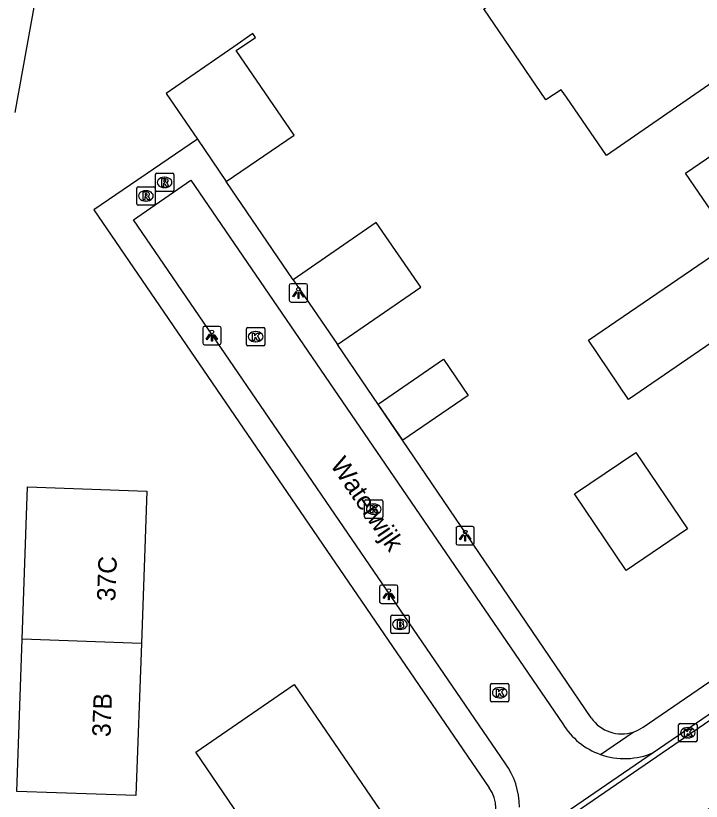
# Model space of a CAD drawing. Extents: x 155275 to 156263, y 382654 to 383635.
# Drawn here: x 155415.06 to 155452.36, y 383301.06 to 383343.77 of the extents above; entities that cross this region are included whole.
import ezdxf

# ---------------------------------------------------------------- set-up
doc = ezdxf.new("R2010")
doc.units = 0
for name, color, linetype in [('IMGEO_Brandkraan', 7, 'Continuous'), ('IMGEO_Kolk', 7, 'Continuous'), ('IMGEO_Lichtpunt', 7, 'Continuous'), ('IMGEO_Openbare_ruimte_label', 7, 'Continuous'), ('IMGEO_Pand', 7, 'Continuous'), ('IMGEO_Pand_nummerreeks', 7, 'Continuous'), ('IMGEO_Rijbaan_lokaal_open', 7, 'Continuous'), ('IMGEO_Rioolput', 7, 'Continuous'), ('IMGEO_Voetpad_open', 7, 'Continuous')]:
    doc.layers.add(name, color=color, linetype=linetype)

msp = doc.modelspace()

# ---------------------------------------------------------------- linework, layer by layer
at = {"layer": 'IMGEO_Brandkraan'}
for p, q in [((155435.463, 383310.256), (155435.463, 383311.108)), ((155435.538, 383311.182), (155436.39, 383311.182)), ((155436.464, 383311.108), (155436.464, 383310.256)), ((155435.951, 383310.962), (155435.976, 383310.962)), ((155435.974, 383310.402), (155435.949, 383310.402)), ((155436.39, 383310.182), (155435.538, 383310.182))]:
    msp.add_line(p, q, dxfattribs=at)
for points in [[(155435.463, 383310.256), (155435.463, 383311.108)], [(155435.538, 383311.182), (155436.39, 383311.182)], [(155436.464, 383311.108), (155436.464, 383310.256)], [(155435.811, 383310.882), (155435.811, 383310.482), (155436.024, 383310.482)], [(155436.042, 383310.882), (155435.811, 383310.882)], [(155435.99, 383310.801), (155435.936, 383310.801), (155435.936, 383310.725)], [(155435.936, 383310.725), (155435.989, 383310.725)], [(155435.998, 383310.649), (155435.936, 383310.649), (155435.936, 383310.568)], [(155435.936, 383310.568), (155435.998, 383310.568)], [(155436.39, 383310.182), (155435.538, 383310.182)]]:
    msp.add_lwpolyline(points, dxfattribs=at)
for centre, radius, start, end in [((155435.54, 383311.106), 0.0765, 91.552, 178.448), ((155435.54, 383311.106), 0.0765, 91.552, 178.448), ((155436.388, 383311.106), 0.0765, 1.552, 88.448), ((155436.388, 383311.106), 0.0765, 1.552, 88.448), ((155435.991, 383310.763), 0.0379, 267.8285, 90.9355), ((155436.046, 383310.737), 0.145, 59.4692, 91.5367), ((155436.071, 383310.784), 0.0922, 285.5137, 58.1501), ((155436.076, 383310.592), 0.105, 301.3115, 78.989), ((155435.54, 383310.258), 0.0765, 181.552, 268.448), ((155435.54, 383310.258), 0.0765, 181.552, 268.448), ((155435.999, 383310.608), 0.0404, 269.8759, 90.5077), ((155436.03, 383310.733), 0.251, 268.6676, 293.5347), ((155436.388, 383310.258), 0.0765, 271.552, 358.448), ((155436.388, 383310.258), 0.0765, 271.552, 358.448)]:
    msp.add_arc(centre, radius, start, end, dxfattribs=at)
for centre, major_axis, ratio, start_param, end_param in [((155435.95, 383310.682), (-0.387, 0.002), 0.722429, 4.712389, 7.853982), ((155435.975, 383310.682), (-0.39, 0.002), 0.717154, 1.570796, 4.712389)]:
    msp.add_ellipse(centre, major_axis=major_axis, ratio=ratio, start_param=start_param, end_param=end_param, dxfattribs=at)
at = {"layer": 'IMGEO_Kolk'}
for p, q in [((155427.619, 383325.892), (155427.619, 383326.744)), ((155427.694, 383326.818), (155428.546, 383326.818)), ((155428.107, 383326.598), (155428.132, 383326.598)), ((155428.62, 383326.744), (155428.62, 383325.892)), ((155428.13, 383326.038), (155428.105, 383326.038)), ((155428.546, 383325.818), (155427.694, 383325.818)), ((155434.04, 383316.517), (155434.04, 383317.369)), ((155434.115, 383317.443), (155434.967, 383317.443)), ((155434.528, 383317.223), (155434.553, 383317.223)), ((155435.041, 383317.369), (155435.041, 383316.517)), ((155434.551, 383316.663), (155434.526, 383316.663)), ((155434.967, 383316.443), (155434.115, 383316.443)), ((155440.892, 383306.541), (155440.892, 383307.393)), ((155440.967, 383307.467), (155441.819, 383307.467)), ((155441.38, 383307.247), (155441.405, 383307.247)), ((155441.893, 383307.393), (155441.893, 383306.541)), ((155441.819, 383306.467), (155440.967, 383306.467)), ((155441.403, 383306.687), (155441.378, 383306.687)), ((155451.127, 383304.363), (155451.127, 383305.215)), ((155451.202, 383305.289), (155452.054, 383305.289)), ((155452.128, 383305.215), (155452.128, 383304.363)), ((155451.615, 383305.069), (155451.64, 383305.069)), ((155452.054, 383304.289), (155451.202, 383304.289)), ((155451.638, 383304.509), (155451.613, 383304.509))]:
    msp.add_line(p, q, dxfattribs=at)
for points in [[(155427.619, 383325.892), (155427.619, 383326.744)], [(155427.694, 383326.818), (155428.546, 383326.818)], [(155427.94, 383326.518), (155428.063, 383326.518), (155428.063, 383326.367), (155428.193, 383326.518), (155428.357, 383326.518), (155428.211, 383326.367), (155428.364, 383326.118), (155428.212, 383326.118), (155428.127, 383326.282), (155428.063, 383326.215), (155428.063, 383326.118), (155427.94, 383326.118), (155427.94, 383326.518)], [(155428.62, 383326.744), (155428.62, 383325.892)], [(155428.546, 383325.818), (155427.694, 383325.818)], [(155434.04, 383316.517), (155434.04, 383317.369)], [(155434.115, 383317.443), (155434.967, 383317.443)], [(155434.361, 383317.143), (155434.484, 383317.143), (155434.484, 383316.992), (155434.614, 383317.143), (155434.778, 383317.143), (155434.632, 383316.992), (155434.785, 383316.743), (155434.633, 383316.743), (155434.548, 383316.907), (155434.484, 383316.84), (155434.484, 383316.743), (155434.361, 383316.743), (155434.361, 383317.143)], [(155435.041, 383317.369), (155435.041, 383316.517)], [(155434.967, 383316.443), (155434.115, 383316.443)], [(155440.892, 383306.541), (155440.892, 383307.393)], [(155440.967, 383307.467), (155441.819, 383307.467)], [(155441.893, 383307.393), (155441.893, 383306.541)], [(155441.213, 383307.167), (155441.336, 383307.167), (155441.336, 383307.016), (155441.466, 383307.167), (155441.63, 383307.167), (155441.484, 383307.016), (155441.637, 383306.767), (155441.485, 383306.767), (155441.4, 383306.931), (155441.336, 383306.864), (155441.336, 383306.767), (155441.213, 383306.767), (155441.213, 383307.167)], [(155441.819, 383306.467), (155440.967, 383306.467)], [(155451.127, 383304.363), (155451.127, 383305.215)], [(155451.202, 383305.289), (155452.054, 383305.289)], [(155452.128, 383305.215), (155452.128, 383304.363)], [(155451.448, 383304.989), (155451.571, 383304.989), (155451.571, 383304.838), (155451.701, 383304.989), (155451.865, 383304.989), (155451.719, 383304.838), (155451.872, 383304.589), (155451.72, 383304.589), (155451.635, 383304.753), (155451.571, 383304.686), (155451.571, 383304.589), (155451.448, 383304.589), (155451.448, 383304.989)], [(155452.054, 383304.289), (155451.202, 383304.289)]]:
    msp.add_lwpolyline(points, dxfattribs=at)
for centre, start, end in [((155427.696, 383326.742), 91.552, 178.448), ((155427.696, 383326.742), 91.552, 178.448), ((155428.544, 383326.742), 1.552, 88.448), ((155428.544, 383326.742), 1.552, 88.448), ((155427.696, 383325.894), 181.552, 268.448), ((155427.696, 383325.894), 181.552, 268.448), ((155428.544, 383325.894), 271.552, 358.448), ((155428.544, 383325.894), 271.552, 358.448), ((155434.117, 383317.367), 91.552, 178.448), ((155434.117, 383317.367), 91.552, 178.448), ((155434.965, 383317.367), 1.552, 88.448), ((155434.965, 383317.367), 1.552, 88.448), ((155434.117, 383316.519), 181.552, 268.448), ((155434.117, 383316.519), 181.552, 268.448), ((155434.965, 383316.519), 271.552, 358.448), ((155434.965, 383316.519), 271.552, 358.448), ((155440.969, 383307.391), 91.552, 178.448), ((155440.969, 383307.391), 91.552, 178.448), ((155441.817, 383307.391), 1.552, 88.448), ((155441.817, 383307.391), 1.552, 88.448), ((155440.969, 383306.543), 181.552, 268.448), ((155440.969, 383306.543), 181.552, 268.448), ((155441.817, 383306.543), 271.552, 358.448), ((155441.817, 383306.543), 271.552, 358.448), ((155451.204, 383305.213), 91.552, 178.448), ((155451.204, 383305.213), 91.552, 178.448), ((155452.052, 383305.213), 1.552, 88.448), ((155452.052, 383305.213), 1.552, 88.448), ((155451.204, 383304.365), 181.552, 268.448), ((155451.204, 383304.365), 181.552, 268.448), ((155452.052, 383304.365), 271.552, 358.448), ((155452.052, 383304.365), 271.552, 358.448)]:
    msp.add_arc(centre, 0.0765, start, end, dxfattribs=at)
for centre, major_axis, ratio, start_param, end_param in [((155428.106, 383326.318), (-0.387, 0.002), 0.722429, 4.712389, 7.853982), ((155428.131, 383326.318), (-0.39, 0.002), 0.717154, 1.570796, 4.712389), ((155434.527, 383316.943), (-0.387, 0.002), 0.722429, 4.712389, 7.853982), ((155434.552, 383316.943), (-0.39, 0.002), 0.717154, 1.570796, 4.712389), ((155441.379, 383306.967), (-0.387, 0.002), 0.722429, 4.712389, 7.853982), ((155441.404, 383306.967), (-0.39, 0.002), 0.717154, 1.570796, 4.712389), ((155451.614, 383304.789), (-0.387, 0.002), 0.722429, 4.712389, 7.853982), ((155451.639, 383304.789), (-0.39, 0.002), 0.717154, 1.570796, 4.712389)]:
    msp.add_ellipse(centre, major_axis=major_axis, ratio=ratio, start_param=start_param, end_param=end_param, dxfattribs=at)
at = {"layer": 'IMGEO_Lichtpunt'}
for p, q in [((155429.947, 383329.102), (155429.947, 383328.295)), ((155429.947, 383329.102), (155429.947, 383328.295)), ((155430.849, 383329.197), (155430.041, 383329.197)), ((155430.849, 383329.197), (155430.041, 383329.197)), ((155430.943, 383328.295), (155430.943, 383329.102)), ((155430.943, 383328.295), (155430.943, 383329.102)), ((155430.041, 383328.201), (155430.849, 383328.201)), ((155430.041, 383328.201), (155430.849, 383328.201)), ((155426.141, 383326.877), (155425.333, 383326.877)), ((155426.141, 383326.877), (155425.333, 383326.877)), ((155425.239, 383326.782), (155425.239, 383325.975)), ((155425.239, 383326.782), (155425.239, 383325.975)), ((155426.235, 383325.975), (155426.235, 383326.782)), ((155426.235, 383325.975), (155426.235, 383326.782)), ((155425.333, 383325.881), (155426.141, 383325.881)), ((155425.333, 383325.881), (155426.141, 383325.881)), ((155439.016, 383315.904), (155439.016, 383315.097)), ((155439.016, 383315.904), (155439.016, 383315.097)), ((155439.918, 383315.999), (155439.11, 383315.999)), ((155439.918, 383315.999), (155439.11, 383315.999)), ((155440.012, 383315.097), (155440.012, 383315.904)), ((155440.012, 383315.097), (155440.012, 383315.904)), ((155439.11, 383315.003), (155439.918, 383315.003)), ((155439.11, 383315.003), (155439.918, 383315.003)), ((155435.762, 383312.813), (155434.954, 383312.813)), ((155435.762, 383312.813), (155434.954, 383312.813)), ((155434.86, 383312.718), (155434.86, 383311.911)), ((155434.86, 383312.718), (155434.86, 383311.911)), ((155435.856, 383311.911), (155435.856, 383312.718)), ((155435.856, 383311.911), (155435.856, 383312.718)), ((155434.954, 383311.817), (155435.762, 383311.817)), ((155434.954, 383311.817), (155435.762, 383311.817))]:
    msp.add_line(p, q, dxfattribs=at)
for points in [[(155430.321, 383328.766), (155430.36, 383328.738), (155430.172, 383328.476), (155430.134, 383328.503), (155430.321, 383328.766)], [(155430.423, 383328.718), (155430.47, 383328.718), (155430.47, 383328.396), (155430.423, 383328.396), (155430.423, 383328.718)], [(155430.533, 383328.738), (155430.571, 383328.765), (155430.758, 383328.503), (155430.719, 383328.475), (155430.533, 383328.738)], [(155425.613, 383326.446), (155425.652, 383326.418), (155425.464, 383326.156), (155425.426, 383326.183), (155425.613, 383326.446)], [(155425.715, 383326.398), (155425.762, 383326.398), (155425.762, 383326.076), (155425.715, 383326.076), (155425.715, 383326.398)], [(155425.825, 383326.418), (155425.863, 383326.445), (155426.05, 383326.183), (155426.011, 383326.155), (155425.825, 383326.418)], [(155439.39, 383315.568), (155439.429, 383315.54), (155439.241, 383315.278), (155439.203, 383315.305), (155439.39, 383315.568)], [(155439.492, 383315.52), (155439.539, 383315.52), (155439.539, 383315.198), (155439.492, 383315.198), (155439.492, 383315.52)], [(155439.602, 383315.54), (155439.64, 383315.567), (155439.827, 383315.305), (155439.788, 383315.277), (155439.602, 383315.54)], [(155435.234, 383312.382), (155435.273, 383312.354), (155435.085, 383312.092), (155435.047, 383312.119), (155435.234, 383312.382)], [(155435.446, 383312.354), (155435.484, 383312.381), (155435.671, 383312.119), (155435.632, 383312.091), (155435.446, 383312.354)], [(155435.336, 383312.334), (155435.383, 383312.334), (155435.383, 383312.012), (155435.336, 383312.012), (155435.336, 383312.334)]]:
    msp.add_lwpolyline(points, dxfattribs=at)
for centre in [(155430.446, 383328.9), (155425.738, 383326.58), (155439.515, 383315.702), (155435.359, 383312.516)]:
    msp.add_circle(centre, 0.0994, dxfattribs=at)
for centre, start, end in [((155430.041, 383329.102), 90, 180), ((155430.041, 383329.102), 90, 180), ((155430.849, 383329.102), 0, 90), ((155430.849, 383329.102), 0, 90), ((155430.041, 383328.295), 180, 270), ((155430.041, 383328.295), 180, 270), ((155430.849, 383328.295), 270, 0), ((155430.849, 383328.295), 270, 360), ((155425.333, 383326.782), 90, 180), ((155425.333, 383326.782), 90, 180), ((155426.141, 383326.782), 0, 90), ((155426.141, 383326.782), 0, 90), ((155425.333, 383325.975), 180, 270), ((155425.333, 383325.975), 180, 270), ((155426.141, 383325.975), 270, 0), ((155426.141, 383325.975), 270, 360), ((155439.11, 383315.904), 90, 180), ((155439.11, 383315.904), 90, 180), ((155439.918, 383315.904), 0, 90), ((155439.918, 383315.904), 0, 90), ((155439.11, 383315.097), 180, 270), ((155439.11, 383315.097), 180, 270), ((155439.918, 383315.097), 270, 0), ((155439.918, 383315.097), 270, 360), ((155434.954, 383312.718), 90, 180), ((155434.954, 383312.718), 90, 180), ((155435.762, 383312.718), 0, 90), ((155435.762, 383312.718), 0, 90), ((155434.954, 383311.911), 180, 270), ((155434.954, 383311.911), 180, 270), ((155435.762, 383311.911), 270, 0), ((155435.762, 383311.911), 270, 360)]:
    msp.add_arc(centre, 0.0946, start, end, dxfattribs=at)
at = {"layer": 'IMGEO_Pand'}
for points in [[(155440.523, 383344.13), (155441.34, 383344.675), (155441.067, 383345.1), (155445.065, 383347.851), (155444.806, 383348.276), (155447.463, 383350.102), (155447.754, 383349.697), (155451.766, 383352.44), (155452.035, 383352.043), (155451.835, 383351.909), (155455.223, 383346.955), (155455.421, 383347.09), (155455.698, 383346.686), (155454.929, 383346.157), (155457.104, 383343.005), (155447.203, 383336.173), (155445.018, 383339.34), (155444.742, 383339.74), (155443.903, 383339.191), (155440.523, 383344.13)], [(155426.522, 383334.751), (155430.206, 383337.265), (155427.061, 383341.874), (155428.1, 383342.584), (155427.959, 383342.791), (155426.924, 383342.074), (155423.258, 383339.534), (155424.949, 383337.057)], [(155454.052, 383331.481), (155451.501, 383335.199), (155461.558, 383342.081), (155465.511, 383336.304), (155461.797, 383333.762), (155462.586, 383332.609), (155448.403, 383322.903), (155446.219, 383326.126), (155454.052, 383331.481)], [(155424.949, 383337.057), (155426.522, 383334.751)], [(155432.572, 383325.887), (155437.099, 383329.002), (155434.678, 383332.519), (155430.165, 383329.414)], [(155430.165, 383329.414), (155432.572, 383325.887)], [(155438.327, 383325.092), (155439.677, 383323.126), (155436.124, 383320.686), (155434.774, 383322.652), (155438.327, 383325.092)], [(155448.797, 383320.027), (155451.612, 383315.865), (155448.28, 383313.611), (155445.465, 383317.773), (155448.797, 383320.027)], [(155415.414, 383309.879), (155415.709, 383318.158), (155422.199, 383317.925), (155421.902, 383309.648)], [(155421.902, 383309.648), (155421.606, 383301.375), (155415.119, 383301.6), (155415.414, 383309.879)], [(155421.902, 383309.648), (155415.414, 383309.879)], [(155430.22, 383307.405), (155435.86, 383299.176), (155433.637, 383297.63), (155430.508, 383295.453), (155424.855, 383303.729), (155430.22, 383307.405)]]:
    msp.add_lwpolyline(points, dxfattribs=at)
at = {"layer": 'IMGEO_Rijbaan_lokaal_open'}
for points in [[(155545.973, 383369.225), (155512.791, 383346.508), (155450.858, 383304.106), (155413.779, 383278.713), (155415.989, 383275.504), (155453.502, 383301.158), (155500.38, 383333.268), (155548.143, 383365.998)], [(155449.748, 383303.711), (155450.724, 383304.38), (155450.774, 383304.414), (155508.223, 383343.736)], [(155441.686, 383303.132), (155421.478, 383332.678), (155424.588, 383334.829), (155444.824, 383305.278)], [(155441.154, 383297.824), (155449.748, 383303.711)]]:
    msp.add_lwpolyline(points, dxfattribs=at)
for centre, radius, start, end in [((155448.188, 383307.32), 3.935, 211.2654, 250.4521), ((155448.184, 383307.302), 3.917, 250.4109, 293.5307), ((155438.476, 383300.77), 3.985, 359.7493, 36.3385)]:
    msp.add_arc(centre, radius, start, end, dxfattribs=at)
at = {"layer": 'IMGEO_Rioolput'}
for p, q in [((155422.663, 383334.276), (155422.663, 383335.128)), ((155422.738, 383335.202), (155423.59, 383335.202)), ((155423.664, 383335.128), (155423.664, 383334.276)), ((155423.151, 383334.982), (155423.176, 383334.982)), ((155421.645, 383333.543), (155421.645, 383334.395)), ((155421.72, 383334.469), (155422.572, 383334.469)), ((155422.133, 383334.249), (155422.158, 383334.249)), ((155422.646, 383334.395), (155422.646, 383333.543)), ((155423.59, 383334.202), (155422.738, 383334.202)), ((155423.174, 383334.422), (155423.149, 383334.422)), ((155422.572, 383333.469), (155421.72, 383333.469)), ((155422.156, 383333.689), (155422.131, 383333.689))]:
    msp.add_line(p, q, dxfattribs=at)
for points in [[(155422.663, 383334.276), (155422.663, 383335.128)], [(155422.738, 383335.202), (155423.59, 383335.202)], [(155423.664, 383335.128), (155423.664, 383334.276)], [(155423.252, 383334.9), (155423, 383334.902), (155423, 383334.502)], [(155423, 383334.502), (155423.124, 383334.502), (155423.124, 383334.664), (155423.135, 383334.664)], [(155423.178, 383334.821), (155423.124, 383334.821), (155423.124, 383334.74)], [(155423.124, 383334.74), (155423.176, 383334.74)], [(155423.182, 383334.635), (155423.253, 383334.502), (155423.393, 383334.502), (155423.328, 383334.628)], [(155421.645, 383333.543), (155421.645, 383334.395)], [(155421.72, 383334.469), (155422.572, 383334.469)], [(155422.234, 383334.167), (155421.982, 383334.169), (155421.982, 383333.769)], [(155422.646, 383334.395), (155422.646, 383333.543)], [(155423.59, 383334.202), (155422.738, 383334.202)], [(155421.982, 383333.769), (155422.106, 383333.769), (155422.106, 383333.931), (155422.117, 383333.931)], [(155422.16, 383334.088), (155422.106, 383334.088), (155422.106, 383334.007)], [(155422.106, 383334.007), (155422.158, 383334.007)], [(155422.164, 383333.902), (155422.235, 383333.769), (155422.375, 383333.769), (155422.31, 383333.895)], [(155422.572, 383333.469), (155421.72, 383333.469)]]:
    msp.add_lwpolyline(points, dxfattribs=at)
for centre, radius, start, end in [((155422.74, 383335.126), 0.0765, 91.552, 178.448), ((155422.74, 383335.126), 0.0765, 91.552, 178.448), ((155423.588, 383335.126), 0.0765, 1.552, 88.448), ((155423.588, 383335.126), 0.0765, 1.552, 88.448), ((155423.134, 383334.611), 0.0533, 26.0293, 88.6989), ((155423.16, 383334.929), 0.19, 274.7715, 282.9687), ((155423.184, 383334.725), 0.0964, 77.0061, 93.1865), ((155423.198, 383334.782), 0.0378, 276.6634, 79.6772), ((155423.251, 383334.79), 0.109, 350.3612, 89.416), ((155423.249, 383334.79), 0.112, 277.5842, 350.9817), ((155423.233, 383334.575), 0.108, 29.5134, 73.7905), ((155421.722, 383334.393), 0.0765, 91.552, 178.448), ((155421.722, 383334.393), 0.0765, 91.552, 178.448), ((155422.233, 383334.057), 0.109, 350.3612, 89.416), ((155422.57, 383334.393), 0.0765, 1.552, 88.448), ((155422.57, 383334.393), 0.0765, 1.552, 88.448), ((155422.74, 383334.278), 0.0765, 181.552, 268.448), ((155422.74, 383334.278), 0.0765, 181.552, 268.448), ((155423.588, 383334.278), 0.0765, 271.552, 358.448), ((155423.588, 383334.278), 0.0765, 271.552, 358.448), ((155422.116, 383333.878), 0.0533, 26.0293, 88.6989), ((155422.142, 383334.196), 0.19, 274.7715, 282.9687), ((155422.166, 383333.992), 0.0964, 77.0061, 93.1865), ((155422.18, 383334.049), 0.0378, 276.6634, 79.6772), ((155422.231, 383334.057), 0.112, 277.5842, 350.9817), ((155422.215, 383333.842), 0.108, 29.5134, 73.7905), ((155421.722, 383333.545), 0.0765, 181.552, 268.448), ((155421.722, 383333.545), 0.0765, 181.552, 268.448), ((155422.57, 383333.545), 0.0765, 271.552, 358.448), ((155422.57, 383333.545), 0.0765, 271.552, 358.448)]:
    msp.add_arc(centre, radius, start, end, dxfattribs=at)
for centre, major_axis, ratio, start_param, end_param in [((155423.15, 383334.702), (-0.387, 0.002), 0.722429, 4.712389, 7.853982), ((155423.175, 383334.702), (-0.39, 0.002), 0.717154, 1.570796, 4.712389), ((155422.132, 383333.969), (-0.387, 0.002), 0.722429, 4.712389, 7.853982), ((155422.157, 383333.969), (-0.39, 0.002), 0.717154, 1.570796, 4.712389)]:
    msp.add_ellipse(centre, major_axis=major_axis, ratio=ratio, start_param=start_param, end_param=end_param, dxfattribs=at)
at = {"layer": 'IMGEO_Voetpad_open'}
for points in [[(155417.323, 383350.75), (155416.901, 383348.781), (155416.529, 383346.862), (155415.01, 383338.5)], [(155424.949, 383337.057), (155419.318, 383333.21), (155440.827, 383301.794)], [(155430.165, 383329.414), (155426.522, 383334.751)], [(155446.376, 383305.594), (155432.572, 383325.887)], [(155449.19, 383305.098), (155476.546, 383323.803)], [(155446.871, 383303.612), (155448.657, 383304.828)]]:
    msp.add_lwpolyline(points, dxfattribs=at)
for centre, radius, start, end in [((155448.028, 383306.734), 2.007, 214.6011, 288.273), ((155448.036, 383306.715), 1.987, 288.218, 305.5125), ((155439.236, 383300.666), 1.95, 326.8138, 35.3263)]:
    msp.add_arc(centre, radius, start, end, dxfattribs=at)

# ---------------------------------------------------------------- texts
at = {"layer": 'IMGEO_Openbare_ruimte_label'}
msp.add_text('Waterwijk', height=1, rotation=304.246, dxfattribs=at).set_placement((155432.142, 383319.349))
at = {"layer": 'IMGEO_Pand_nummerreeks'}
for s, p in [('37C', (155420.483, 383311.925)), ('37B', (155420.219, 383304.551))]:
    msp.add_text(s, height=1, rotation=87.949, dxfattribs=at).set_placement(p)

doc.saveas('drawing.dxf')
